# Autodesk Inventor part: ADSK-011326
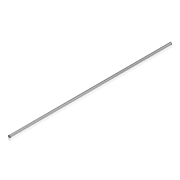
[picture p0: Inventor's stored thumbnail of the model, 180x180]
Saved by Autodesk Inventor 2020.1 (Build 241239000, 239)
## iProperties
Created: 1999-12
Part Number: ADSK-011326
Material: Pearson DGP
Description: SHFTTA,RG,AX,697,10,EE
Document SubType Name: Modeling
Designer: sspink
Density: 7.83 g/cm^3
Appearance: Chrom - poliert
Mass: 6768.53 g
Surface Area: 1421.57 cm^2
Volume: 864.436 cm^3
Control State: 0
Checked Out: False
Last Check In By: sspink
Last Check In Date: 1999-12-22
Master: False
Shininess: 60.0
Length Units: 11269
Angle Units: 11279
Time Units: 11290
Mass Units: 11283
Length Display Precision: 3
Angle Display Precision: 2
Compacted: True
Dimensions: 25x25x1772 mm
Mass: 6,769 kg
DocNumber: ADSK-011326.ipt
Folder: 01 - Themengebiete\Simplification\01 - Packaging machine\
VDS_Category: 3D Komponenten
Density: 7.83
Volumn: 892.9961280870174
Area: 1440.2869687978057
PropertySet Name: Model Information
Author: sspink
Revision Number: -
Title: shaft
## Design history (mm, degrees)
node "Solide1"
  node "Extrusion1" dims "d1" = 1772, "d2" = 0
  node "Hole1" dims "d3" = 10.106, "d4" = 9.525, "d5" = 6.35, "d6" = 60 deg, "d7" = 32.3, "d8" = 118 deg, "d18" = 24
  node "Hole2" dims "d9" = 10.106, "d10" = 9.525, "d11" = 6.35, "d12" = 60 deg, "d13" = 32.3, "d14" = 118 deg, "d19" = 24
  node "Chamfer1" dims "d15" = 0.79375, "d16" = 0.79375, "d17" = 45 deg
sketch "Sketch1"
  geometry: C1 r 12.5 at (46.31, 24.424)
  constraints: 1 centre point
  dimensions: "d0" = 25 diameter of C1
node "Corps solides"
node "Corps surfaciques"
sketch "Sketch2"
  geometry: C1 r 12.5 at (0, 0) reference; 1 further point
  constraints: 1 coincident
sketch "Sketch3"
  geometry: C1 r 12.5 at (0, 0) reference; 1 further point
  constraints: 1 coincident
